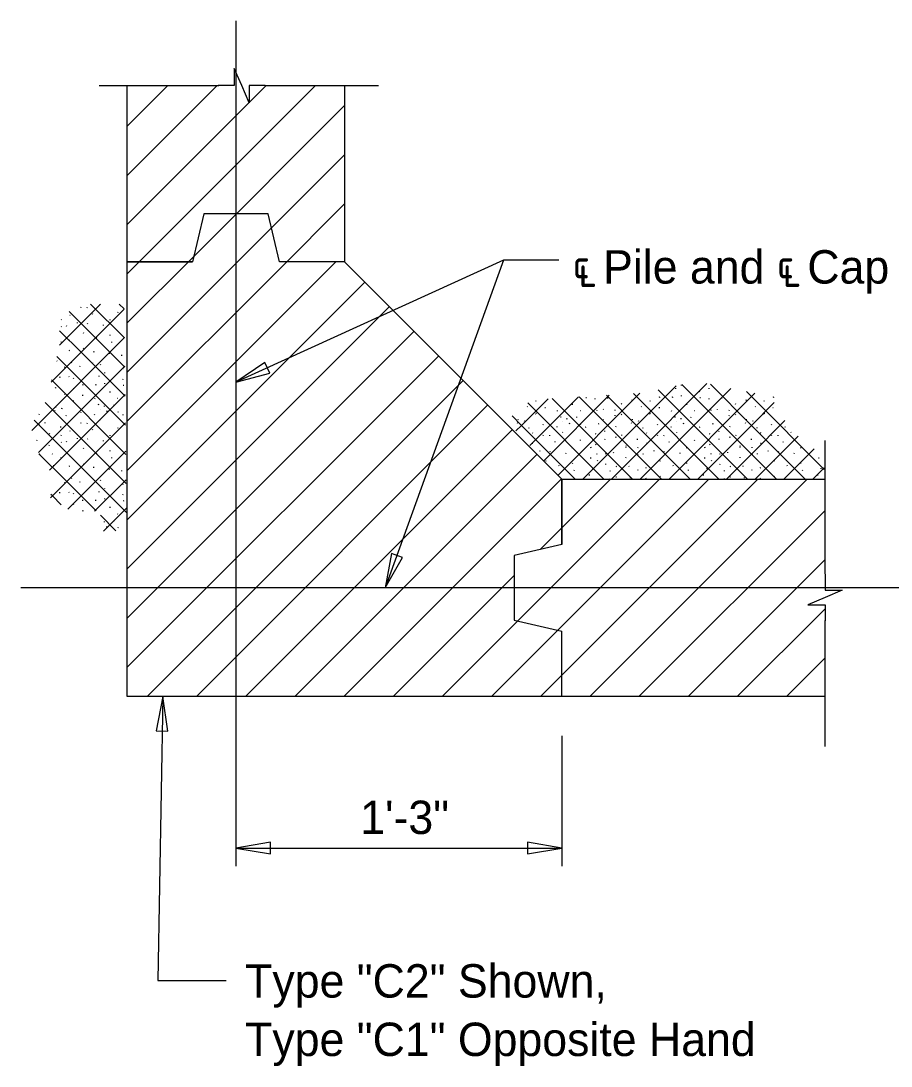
# Model space of a CAD drawing. Extents: x 0.4 to 30.4, y 0.1 to 19.4.
# Drawn here: x 0.429 to 4.371, y 0.449 to 5.182 of the extents above; entities that cross this region are included whole.
import ezdxf

# ---------------------------------------------------------------- set-up
doc = ezdxf.new("R2010")
doc.units = 0
for name, color, linetype in [('Dimension', 7, 'Continuous'), ('Miscellaneous', 7, 'Continuous'), ('SheetPileConc', 7, 'Continuous'), ('TextStructures', 7, 'Continuous')]:
    doc.layers.add(name, color=color, linetype=linetype)

msp = doc.modelspace()

# ---------------------------------------------------------------- linework, layer by layer
at = {"layer": 'Dimension'}
for p, q in [((0.7839, 4.8887), (1.3252, 4.8887)), ((1.5358, 4.8887), (2.0493, 4.8887)), ((2.6158, 4.0988), (1.4035, 3.5464)), ((2.6158, 4.0988), (2.0793, 2.6144)), ((2.8656, 4.0988), (2.6158, 4.0988)), ((4.0715, 2.6773), (4.0715, 3.2816)), ((4.0715, 1.8953), (4.0715, 2.4666)), ((2.8801, 1.9439), (2.8801, 1.3534)), ((1.4035, 1.4362), (2.8801, 1.4362))]:
    msp.add_line(p, q, dxfattribs=at)
for points in [[(1.5355, 4.8887), (1.463, 4.8887), (1.463, 4.8112), (1.4293, 4.8887), (1.3955, 4.9662), (1.3955, 4.8887), (1.323, 4.8887)], [(4.0715, 2.677), (4.0715, 2.6045), (4.149, 2.6045), (4.0715, 2.5708), (3.994, 2.537), (4.0715, 2.537), (4.0715, 2.4645)], [(1.0723, 2.1223), (1.0492, 0.8364), (1.3598, 0.8364)]]:
    msp.add_lwpolyline(points, dxfattribs=at)
for points in [[(1.4035, 3.5464), (1.5566, 3.5871), (1.5347, 3.6353)], [(2.0793, 2.6145), (2.1573, 2.7524), (2.1075, 2.7704)], [(1.0723, 2.1223), (1.0422, 1.9668), (1.0951, 1.9655)], [(1.4035, 1.4362), (1.5597, 1.4097), (1.5597, 1.4626)], [(2.8801, 1.4362), (2.7239, 1.4626), (2.7239, 1.4097)]]:
    msp.add_lwpolyline(points, close=True, dxfattribs=at)
at = {"layer": 'Miscellaneous'}
for p, q in [((1.4035, 5.1817), (1.4035, 1.3534)), ((0.9113, 4.2594), (1.5406, 4.8887)), ((0.9113, 4.4822), (1.3179, 4.8887)), ((0.9113, 4.7049), (1.0951, 4.8887)), ((0.9114, 4.0368), (1.7633, 4.8887)), ((1.2123, 4.1149), (1.8957, 4.7984)), ((1.5642, 4.2441), (1.8957, 4.5756)), ((1.5901, 4.0472), (1.8957, 4.3529)), ((0.9114, 3.5913), (1.5642, 4.2441)), ((0.9114, 3.8141), (1.2123, 4.1149)), ((0.9114, 3.1458), (1.8565, 4.091)), ((0.9114, 3.3685), (1.6339, 4.091)), ((0.9114, 2.9231), (1.9875, 3.9992)), ((0.604, 3.7137), (0.7898, 3.8996)), ((0.7005, 3.8838), (0.702, 3.8868)), ((0.7299, 3.8821), (0.7307, 3.8852)), ((0.8981, 3.7461), (0.7446, 3.8996)), ((0.7888, 3.8974), (0.788, 3.8989)), ((0.8965, 3.8779), (0.8748, 3.8996)), ((0.9114, 2.7004), (2.0989, 3.8879)), ((0.8323, 3.6816), (0.6482, 3.8658)), ((0.6532, 3.847), (0.6509, 3.8478)), ((0.7021, 3.6816), (0.8965, 3.8761)), ((0.7538, 3.8539), (0.7545, 3.8569)), ((0.8688, 3.8608), (0.8696, 3.8638)), ((0.614, 3.7974), (0.611, 3.7966)), ((0.6121, 3.828), (0.6127, 3.8303)), ((0.6366, 3.7989), (0.6373, 3.8019)), ((0.6854, 3.8124), (0.6862, 3.8154)), ((0.7316, 3.8103), (0.7331, 3.8133)), ((0.8031, 3.8019), (0.8038, 3.8049)), ((0.8331, 3.8259), (0.8339, 3.8289)), ((0.7021, 3.6816), (0.6048, 3.7789)), ((0.7122, 3.7681), (0.7137, 3.7711)), ((0.773, 3.7447), (0.7715, 3.747)), ((0.8323, 3.6816), (0.8981, 3.7474)), ((0.8331, 3.7567), (0.8339, 3.7597)), ((0.9113, 2.4776), (2.2102, 3.7765)), ((0.6117, 3.7267), (0.6133, 3.7297)), ((0.6501, 3.7364), (0.6471, 3.7349)), ((0.7138, 3.6974), (0.7123, 3.6996)), ((0.8407, 3.7248), (0.8415, 3.7277)), ((0.5719, 3.4211), (0.8323, 3.6816)), ((0.5719, 3.5514), (0.7021, 3.6816)), ((0.9029, 3.3506), (0.5922, 3.6613)), ((0.6501, 3.689), (0.6471, 3.6876)), ((0.9013, 3.4824), (0.7021, 3.6816)), ((0.7609, 3.6831), (0.7572, 3.6823)), ((0.8301, 3.674), (0.8309, 3.6771)), ((0.8997, 3.6142), (0.8323, 3.6816)), ((0.8858, 3.6657), (0.8865, 3.6688)), ((0.9113, 2.2548), (2.3216, 3.6651)), ((0.5719, 3.2909), (0.8996, 3.6187)), ((0.5937, 3.641), (0.5922, 3.6417)), ((0.6283, 3.6138), (0.6253, 3.6124)), ((0.6599, 3.6327), (0.6591, 3.6342)), ((0.6967, 3.6161), (0.6974, 3.6191)), ((0.7541, 3.6321), (0.7549, 3.6351)), ((0.7903, 3.6244), (0.791, 3.6274)), ((0.891, 3.6056), (0.8925, 3.6086)), ((0.566, 3.5455), (0.5719, 3.5514)), ((0.5719, 3.5514), (0.5682, 3.5551)), ((0.9045, 3.2188), (0.5719, 3.5514)), ((0.6065, 3.568), (0.6028, 3.5673)), ((0.6486, 3.5695), (0.6471, 3.5718)), ((0.6673, 3.5627), (0.6689, 3.5657)), ((0.7835, 3.5718), (0.7842, 3.5748)), ((0.8091, 3.5868), (0.8098, 3.5898)), ((0.891, 3.5582), (0.8925, 3.5612)), ((1.0015, 2.1223), (2.433, 3.5537)), ((0.5854, 3.5199), (0.5869, 3.5229)), ((0.5869, 3.5184), (0.5877, 3.5214)), ((0.6673, 3.5153), (0.6689, 3.5184)), ((0.7108, 3.5334), (0.707, 3.5327)), ((0.77, 3.5334), (0.7662, 3.5327)), ((0.8091, 3.5386), (0.8098, 3.5417)), ((0.8963, 3.5312), (0.8933, 3.5304)), ((3.2174, 3.2197), (3.5368, 3.5392)), ((3.2174, 3.3499), (3.3973, 3.5299)), ((3.2349, 3.107), (3.6452, 3.5173)), ((3.721, 3.1068), (3.3165, 3.5114)), ((3.3954, 3.5158), (3.3961, 3.5188)), ((3.421, 3.5308), (3.4217, 3.5338)), ((3.7383, 3.2197), (3.4224, 3.5356)), ((3.5029, 3.5023), (3.5044, 3.5053)), ((3.5473, 3.5158), (3.5473, 3.5188)), ((3.7383, 3.3499), (3.5521, 3.5361)), ((3.7383, 3.4802), (3.7153, 3.5032)), ((0.5719, 3.1607), (0.9012, 3.4901)), ((0.6283, 3.4898), (0.6268, 3.4921)), ((0.6666, 3.4575), (0.6659, 3.459)), ((0.6697, 3.4597), (0.6666, 3.4597)), ((0.7108, 3.486), (0.707, 3.4853)), ((0.7643, 3.4703), (0.7651, 3.4733)), ((0.8346, 3.5011), (0.8301, 3.5011)), ((0.8685, 3.4718), (0.867, 3.4725)), ((2.6966, 3.3499), (2.8168, 3.4702)), ((2.7351, 3.2583), (2.9555, 3.4787)), ((2.7623, 3.4594), (2.7639, 3.4624)), ((2.7987, 3.1917), (3.0942, 3.4872)), ((3.1999, 3.107), (2.8357, 3.4714)), ((2.8624, 3.1251), (3.2174, 3.4802)), ((3.2174, 3.2197), (2.9583, 3.4789)), ((2.9913, 3.4752), (2.9883, 3.4745)), ((3.0304, 3.4684), (3.0304, 3.4714)), ((3.2174, 3.3499), (3.081, 3.4864)), ((3.089, 3.4737), (3.0853, 3.4729)), ((3.1973, 3.4639), (3.1988, 3.4669)), ((3.1988, 3.4624), (3.1995, 3.4654)), ((3.2174, 3.4802), (3.2037, 3.4939)), ((3.2174, 3.4802), (3.2329, 3.4957)), ((3.5908, 3.1068), (3.2174, 3.4802)), ((3.2792, 3.4594), (3.2808, 3.4624)), ((3.3227, 3.4775), (3.3189, 3.4767)), ((3.365, 3.1069), (3.7383, 3.4802)), ((3.3819, 3.4775), (3.3781, 3.4767)), ((3.421, 3.4827), (3.4217, 3.4857)), ((3.5082, 3.4752), (3.5052, 3.4745)), ((3.5473, 3.4684), (3.5473, 3.4714)), ((3.6059, 3.4737), (3.6022, 3.4729)), ((3.7142, 3.4639), (3.7157, 3.4669)), ((3.7157, 3.4624), (3.7164, 3.4654)), ((3.7383, 3.4802), (3.7535, 3.4955)), ((4.0676, 3.1508), (3.7383, 3.4802)), ((3.7961, 3.4594), (3.7977, 3.4624)), ((3.8396, 3.4775), (3.8358, 3.4767)), ((0.4782, 3.3274), (0.5719, 3.4212)), ((0.5719, 3.4211), (0.5387, 3.4543)), ((0.8323, 3.1607), (0.5719, 3.4212)), ((0.5832, 3.4154), (0.5847, 3.4184)), ((0.5869, 3.4312), (0.5877, 3.4342)), ((0.6155, 3.4251), (0.617, 3.4289)), ((0.7005, 3.4079), (0.702, 3.4109)), ((0.782, 3.4439), (0.7783, 3.4432)), ((0.7888, 3.4214), (0.7883, 3.4222)), ((0.8076, 3.4349), (0.8083, 3.4379)), ((0.8189, 3.4131), (0.8204, 3.4169)), ((0.852, 3.4417), (0.8527, 3.4446)), ((0.8693, 3.4101), (0.8708, 3.4131)), ((1.2243, 2.1223), (2.5443, 3.4424)), ((2.7233, 3.4338), (2.7218, 3.4361)), ((3.0697, 3.1071), (2.725, 3.4518)), ((2.8058, 3.4301), (2.802, 3.4293)), ((2.8593, 3.4143), (2.8601, 3.4173)), ((2.9296, 3.4451), (2.9251, 3.4451)), ((2.9635, 3.4158), (2.962, 3.4165)), ((3.0386, 3.4173), (3.0394, 3.4203)), ((3.068, 3.4218), (3.0673, 3.4233)), ((3.1206, 3.4173), (3.1214, 3.4203)), ((3.1484, 3.4459), (3.1507, 3.4488)), ((3.2402, 3.4338), (3.2387, 3.4361)), ((3.3227, 3.4301), (3.3189, 3.4293)), ((3.3762, 3.4143), (3.377, 3.4173)), ((3.4465, 3.4451), (3.442, 3.4451)), ((3.4804, 3.4158), (3.4789, 3.4165)), ((3.5555, 3.4173), (3.5563, 3.4203)), ((3.5849, 3.4218), (3.5842, 3.4233)), ((3.6375, 3.4173), (3.6383, 3.4203)), ((3.6653, 3.4459), (3.6676, 3.4488)), ((3.7383, 3.3499), (3.8418, 3.4535)), ((3.7571, 3.4338), (3.7556, 3.4361)), ((3.837, 3.4295), (3.8358, 3.4293)), ((0.5719, 3.2909), (0.4889, 3.374)), ((0.5117, 3.3988), (0.5133, 3.4025)), ((0.5388, 3.3598), (0.5395, 3.3627)), ((0.6351, 3.3928), (0.6358, 3.3958)), ((0.6532, 3.371), (0.6509, 3.3717)), ((0.7005, 3.3605), (0.702, 3.3635)), ((0.7021, 3.1607), (0.9028, 3.3614)), ((0.7299, 3.3588), (0.7307, 3.3618)), ((0.7628, 3.3973), (0.7635, 3.4004)), ((0.7888, 3.374), (0.788, 3.3755)), ((0.8933, 3.3973), (0.8896, 3.3965)), ((2.6966, 3.3499), (2.654, 3.3926)), ((2.6782, 3.3594), (2.6797, 3.3624)), ((2.6819, 3.3752), (2.6827, 3.3782)), ((2.7105, 3.3691), (2.712, 3.3729)), ((2.7616, 3.4015), (2.7609, 3.403)), ((2.7647, 3.4038), (2.7616, 3.4038)), ((2.877, 3.3879), (2.8732, 3.3872)), ((2.8838, 3.3654), (2.8833, 3.3662)), ((2.9025, 3.3789), (2.9033, 3.382)), ((2.9139, 3.3571), (2.9154, 3.3609)), ((2.9469, 3.3857), (2.9477, 3.3887)), ((3.068, 3.3745), (3.0673, 3.376)), ((3.1206, 3.3932), (3.1214, 3.3962)), ((3.1484, 3.3985), (3.1507, 3.4015)), ((3.1951, 3.3594), (3.1966, 3.3624)), ((3.1988, 3.3752), (3.1995, 3.3782)), ((3.2274, 3.3691), (3.2289, 3.3729)), ((3.2785, 3.4015), (3.2778, 3.403)), ((3.2816, 3.4038), (3.2785, 3.4038)), ((3.3939, 3.3879), (3.3901, 3.3872)), ((3.4007, 3.3654), (3.4002, 3.3662)), ((3.4194, 3.3789), (3.4202, 3.382)), ((3.4308, 3.3571), (3.4323, 3.3609)), ((3.4638, 3.3857), (3.4646, 3.3887)), ((3.5849, 3.3745), (3.5842, 3.376)), ((3.6375, 3.3932), (3.6383, 3.3962)), ((3.6653, 3.3985), (3.6676, 3.4015)), ((3.712, 3.3594), (3.7134, 3.3624)), ((3.7157, 3.3752), (3.7164, 3.3782)), ((3.7383, 3.2197), (3.89, 3.3715)), ((3.7443, 3.3691), (3.7458, 3.3729)), ((3.7954, 3.4015), (3.7947, 3.403)), ((3.7985, 3.4038), (3.7954, 3.4038)), ((0.5117, 3.3514), (0.5133, 3.3552)), ((0.5591, 3.3116), (0.5599, 3.3146)), ((0.611, 3.3424), (0.6072, 3.3417)), ((0.6532, 3.3236), (0.6509, 3.3244)), ((0.7538, 3.3305), (0.7545, 3.3335)), ((0.8688, 3.3375), (0.8696, 3.3404)), ((1.447, 2.1223), (2.6557, 3.331)), ((2.6714, 3.3248), (2.6966, 3.35)), ((2.9394, 3.1071), (2.6966, 3.35)), ((2.7301, 3.3368), (2.7308, 3.3399)), ((2.7482, 3.3151), (2.7459, 3.3158)), ((2.7955, 3.3519), (2.797, 3.3549)), ((2.8578, 3.3414), (2.8585, 3.3444)), ((2.8838, 3.318), (2.883, 3.3195)), ((2.9643, 3.3541), (2.9658, 3.3571)), ((2.9746, 3.1071), (3.2174, 3.35)), ((2.9883, 3.3414), (2.9846, 3.3406)), ((3.0477, 3.3571), (3.044, 3.3556)), ((3.074, 3.3226), (3.0748, 3.3255)), ((3.1236, 3.3429), (3.1252, 3.3466)), ((3.4605, 3.1069), (3.2174, 3.35)), ((3.2469, 3.3368), (3.2477, 3.3399)), ((3.265, 3.3151), (3.2628, 3.3158)), ((3.3124, 3.3519), (3.3139, 3.3549)), ((3.3747, 3.3414), (3.3754, 3.3444)), ((3.4007, 3.318), (3.3999, 3.3195)), ((3.4812, 3.3541), (3.4827, 3.3571)), ((3.4952, 3.1069), (3.7383, 3.35)), ((3.5052, 3.3414), (3.5015, 3.3406)), ((3.5646, 3.3571), (3.5608, 3.3556)), ((3.5909, 3.3226), (3.5917, 3.3255)), ((3.6405, 3.3429), (3.6421, 3.3466)), ((3.9816, 3.1066), (3.7383, 3.35)), ((3.7638, 3.3368), (3.7646, 3.3399)), ((3.7819, 3.3151), (3.7797, 3.3158)), ((3.8293, 3.3519), (3.8308, 3.3549)), ((3.8916, 3.3414), (3.8923, 3.3444)), ((3.9176, 3.318), (3.9168, 3.3195)), ((0.5019, 3.2812), (0.5027, 3.2841)), ((0.5089, 3.228), (0.5719, 3.2909)), ((0.5576, 3.3063), (0.5591, 3.3094)), ((0.7021, 3.1607), (0.5719, 3.2909)), ((0.614, 3.274), (0.611, 3.2732)), ((0.6121, 3.3046), (0.6129, 3.3076)), ((0.6366, 3.2755), (0.6373, 3.2785)), ((0.6854, 3.2891), (0.6862, 3.2921)), ((0.7316, 3.2869), (0.7331, 3.2899)), ((0.8031, 3.2785), (0.8038, 3.2815)), ((0.8331, 3.3025), (0.8339, 3.3056)), ((2.7482, 3.2677), (2.7459, 3.2684)), ((2.7955, 3.3045), (2.797, 3.3075)), ((2.8249, 3.3028), (2.8257, 3.3059)), ((2.8488, 3.2746), (2.8495, 3.2776)), ((2.9638, 3.2815), (2.9646, 3.2845)), ((3.0342, 3.3098), (3.0319, 3.3121)), ((3.0748, 3.2857), (3.0755, 3.2887)), ((3.1236, 3.2955), (3.1252, 3.2992)), ((3.1507, 3.3038), (3.1514, 3.3067)), ((3.2229, 3.2864), (3.2191, 3.2857)), ((3.265, 3.2677), (3.2628, 3.2684)), ((3.3124, 3.3045), (3.3139, 3.3075)), ((3.3418, 3.3028), (3.3426, 3.3059)), ((3.3657, 3.2746), (3.3664, 3.2776)), ((3.4807, 3.2815), (3.4815, 3.2845)), ((3.5511, 3.3098), (3.5488, 3.3121)), ((3.5917, 3.2857), (3.5924, 3.2887)), ((3.6405, 3.2955), (3.6421, 3.2992)), ((3.6676, 3.3038), (3.6683, 3.3067)), ((3.7398, 3.2864), (3.736, 3.2857)), ((3.7555, 3.1068), (3.9506, 3.3019)), ((3.7819, 3.2677), (3.7797, 3.2684)), ((3.8293, 3.3045), (3.8308, 3.3075)), ((3.8587, 3.3028), (3.8595, 3.3059)), ((3.8826, 3.2746), (3.8833, 3.2776)), ((0.5716, 3.161), (0.5109, 3.2217)), ((0.5147, 3.2191), (0.5119, 3.2184)), ((0.5576, 3.259), (0.5591, 3.262)), ((0.5727, 3.2191), (0.5704, 3.2214)), ((0.7122, 3.2447), (0.7137, 3.2477)), ((0.773, 3.2214), (0.7715, 3.2236)), ((0.8323, 3.1607), (0.9043, 3.2327)), ((0.8331, 3.2334), (0.8339, 3.2364)), ((1.6697, 2.1223), (2.7671, 3.2197)), ((2.7804, 3.2331), (2.7812, 3.2361)), ((2.8266, 3.2309), (2.8281, 3.2339)), ((2.8981, 3.2225), (2.8988, 3.2255)), ((2.9281, 3.2466), (2.9288, 3.2496)), ((3.0116, 3.2496), (3.0078, 3.2488)), ((3.0342, 3.2624), (3.0319, 3.2647)), ((3.0386, 3.2203), (3.0394, 3.2233)), ((3.0785, 3.2203), (3.0792, 3.2233)), ((3.1048, 3.1071), (3.2174, 3.2197)), ((3.1138, 3.2252), (3.1146, 3.2281)), ((3.1695, 3.2503), (3.171, 3.2534)), ((3.171, 3.2556), (3.1718, 3.2587)), ((3.3302, 3.107), (3.2174, 3.2197)), ((3.224, 3.2486), (3.2247, 3.2516)), ((3.2484, 3.2195), (3.2492, 3.2225)), ((3.2973, 3.2331), (3.2981, 3.2361)), ((3.3435, 3.2309), (3.345, 3.2339)), ((3.4149, 3.2225), (3.4157, 3.2255)), ((3.445, 3.2466), (3.4457, 3.2496)), ((3.5285, 3.2496), (3.5247, 3.2488)), ((3.5511, 3.2624), (3.5488, 3.2647)), ((3.5555, 3.2203), (3.5563, 3.2233)), ((3.5954, 3.2203), (3.5961, 3.2233)), ((3.6253, 3.1068), (3.7383, 3.2197)), ((3.6307, 3.2252), (3.6315, 3.2281)), ((3.6864, 3.2503), (3.6879, 3.2534)), ((3.6879, 3.2556), (3.6886, 3.2587)), ((3.8513, 3.1067), (3.7383, 3.2197)), ((3.7409, 3.2486), (3.7416, 3.2516)), ((3.7653, 3.2195), (3.7661, 3.2225)), ((3.8142, 3.2331), (3.815, 3.2361)), ((3.8604, 3.2309), (3.8619, 3.2339)), ((3.8856, 3.1067), (4.0221, 3.2432)), ((3.9318, 3.2225), (3.9326, 3.2255)), ((3.9619, 3.2466), (3.9626, 3.2496)), ((0.6117, 3.2033), (0.6133, 3.2063)), ((0.6501, 3.2131), (0.6471, 3.2116)), ((0.7138, 3.174), (0.7123, 3.1762)), ((0.8407, 3.2014), (0.8415, 3.2044)), ((2.8072, 3.1887), (2.8087, 3.1917)), ((2.9281, 3.1774), (2.9288, 3.1804)), ((3.0116, 3.2023), (3.0078, 3.2015)), ((3.0412, 3.1901), (3.0419, 3.193)), ((3.0785, 3.1729), (3.0792, 3.1759)), ((3.1695, 3.203), (3.171, 3.206)), ((3.2259, 3.218), (3.2229, 3.2173)), ((3.3241, 3.1887), (3.3256, 3.1917)), ((3.445, 3.1774), (3.4457, 3.1804)), ((3.5285, 3.2023), (3.5247, 3.2015)), ((3.558, 3.1901), (3.5588, 3.193)), ((3.5954, 3.1729), (3.5961, 3.1759)), ((3.6864, 3.203), (3.6879, 3.206)), ((3.7428, 3.218), (3.7398, 3.2173)), ((3.841, 3.1887), (3.8425, 3.1917)), ((3.9619, 3.1774), (3.9626, 3.1804)), ((4.0454, 3.2023), (4.0416, 3.2015)), ((0.5584, 3.1472), (0.5719, 3.1607)), ((0.7699, 2.9627), (0.5719, 3.1607)), ((0.5719, 3.0305), (0.7021, 3.1607)), ((0.5779, 3.1673), (0.5787, 3.1702)), ((0.6423, 2.9707), (0.8323, 3.1607)), ((0.6501, 3.1657), (0.6471, 3.1643)), ((0.9077, 2.9551), (0.7021, 3.1607)), ((0.7609, 3.1598), (0.7572, 3.159)), ((0.8301, 3.1506), (0.8309, 3.1537)), ((0.9061, 3.0869), (0.8323, 3.1607)), ((0.8858, 3.1424), (0.8865, 3.1454)), ((2.868, 3.1654), (2.8665, 3.1677)), ((2.9357, 3.1455), (2.9365, 3.1484)), ((3.0063, 3.1248), (3.0018, 3.124)), ((3.0199, 3.1534), (3.0206, 3.1563)), ((3.0988, 3.1421), (3.0995, 3.1451)), ((3.1266, 3.1632), (3.1236, 3.1624)), ((3.1846, 3.1632), (3.1823, 3.1654)), ((3.2236, 3.1473), (3.2252, 3.1503)), ((3.262, 3.1571), (3.259, 3.1556)), ((3.3849, 3.1654), (3.3834, 3.1677)), ((3.4526, 3.1455), (3.4534, 3.1484)), ((3.5232, 3.1248), (3.5187, 3.124)), ((3.5368, 3.1534), (3.5375, 3.1563)), ((3.6157, 3.1421), (3.6164, 3.1451)), ((3.6435, 3.1632), (3.6405, 3.1624)), ((3.7015, 3.1632), (3.6992, 3.1654)), ((3.7405, 3.1473), (3.7421, 3.1503)), ((3.7789, 3.1571), (3.7759, 3.1556)), ((3.9018, 3.1654), (3.9003, 3.1677)), ((3.9695, 3.1455), (3.9703, 3.1484)), ((4.0158, 3.1066), (4.067, 3.1579)), ((4.0401, 3.1248), (4.0356, 3.124)), ((4.0537, 3.1534), (4.0544, 3.1563)), ((0.6283, 3.0905), (0.6253, 3.0891)), ((0.6599, 3.1093), (0.6591, 3.1108)), ((0.6967, 3.0928), (0.6974, 3.0958)), ((0.7541, 3.1088), (0.7549, 3.1118)), ((0.7632, 2.9614), (0.9059, 3.1041)), ((0.7903, 3.101), (0.791, 3.1041)), ((0.891, 3.0822), (0.8925, 3.0853)), ((1.8925, 2.1223), (2.8785, 3.1083)), ((2.6804, 2.4647), (3.3223, 3.1066)), ((2.7807, 2.7879), (3.0995, 3.1066)), ((2.7834, 2.1223), (3.7678, 3.1066)), ((2.8606, 2.4222), (3.545, 3.1066)), ((3.0061, 2.1223), (3.9905, 3.1066)), ((3.0989, 3.1071), (3.0995, 3.1097)), ((3.1266, 3.1158), (3.1236, 3.115)), ((3.1898, 3.1113), (3.1906, 3.1143)), ((3.262, 3.1097), (3.259, 3.1083)), ((3.3257, 3.118), (3.3242, 3.1203)), ((3.6157, 3.1068), (3.6164, 3.1097)), ((3.6435, 3.1158), (3.6405, 3.115)), ((3.7067, 3.1113), (3.7075, 3.1143)), ((3.7789, 3.1097), (3.7759, 3.1083)), ((3.8426, 3.118), (3.8411, 3.1203)), ((0.5634, 3.022), (0.5719, 3.0305)), ((0.5719, 3.0305), (0.5653, 3.0371)), ((0.6119, 2.9905), (0.5719, 3.0305)), ((0.6065, 3.0447), (0.6028, 3.0439)), ((0.6486, 3.0462), (0.6471, 3.0484)), ((0.6673, 3.0394), (0.6689, 3.0424)), ((0.7835, 3.0484), (0.7842, 3.0514)), ((0.8091, 3.0635), (0.8098, 3.0665)), ((0.891, 3.0349), (0.8925, 3.0379)), ((0.6673, 2.992), (0.6689, 2.9951)), ((0.7108, 3.0101), (0.707, 3.0093)), ((0.77, 3.0101), (0.7662, 3.0093)), ((0.8091, 3.0153), (0.8098, 3.0184)), ((0.8963, 3.0078), (0.8933, 3.0071)), ((0.7108, 2.9627), (0.707, 2.9619)), ((0.8593, 2.8733), (0.7893, 2.9433)), ((0.8036, 2.8716), (0.9074, 2.9754)), ((0.8346, 2.9777), (0.8301, 2.9777)), ((0.8685, 2.9484), (0.867, 2.9492)), ((3.2289, 2.1223), (4.0715, 2.9649)), ((0.8076, 2.9115), (0.8083, 2.9146)), ((0.8189, 2.8897), (0.8204, 2.8935)), ((0.852, 2.9184), (0.8527, 2.9213)), ((0.8693, 2.8867), (0.8708, 2.8897)), ((3.4516, 2.1223), (4.0715, 2.7422)), ((2.1152, 2.1223), (2.6635, 2.6706)), ((4.0715, 2.6144), (0.4294, 2.6144)), ((4.4653, 2.6144), (4.0715, 2.6144)), ((3.6743, 2.1223), (4.0715, 2.5195)), ((2.3379, 2.1223), (2.6804, 2.4648)), ((2.5606, 2.1223), (2.8606, 2.4222)), ((3.8971, 2.1223), (4.0715, 2.2967))]:
    msp.add_line(p, q, dxfattribs=at)
at = {"layer": 'SheetPileConc'}
for p, q in [((0.9113, 4.091), (0.9113, 4.8887)), ((1.8957, 4.8887), (1.8957, 4.091)), ((1.2578, 4.3076), (1.2066, 4.091)), ((1.5492, 4.3076), (1.2578, 4.3076)), ((1.6004, 4.091), (1.5492, 4.3076)), ((0.9113, 2.1223), (0.9114, 4.091)), ((1.2066, 4.091), (0.9113, 4.091)), ((0.9113, 4.091), (1.2066, 4.091)), ((1.2067, 4.091), (0.9114, 4.091)), ((1.8957, 4.091), (1.6004, 4.091)), ((1.8957, 4.091), (1.6004, 4.091)), ((1.8957, 4.091), (1.6004, 4.091)), ((2.8801, 3.1067), (1.8957, 4.091)), ((2.8801, 2.8113), (2.8801, 3.1067)), ((2.8801, 3.1066), (2.8801, 2.8113)), ((2.8801, 3.1066), (4.0715, 3.1066)), ((2.8801, 2.8113), (2.6635, 2.7601)), ((2.6635, 2.7601), (2.6636, 2.4687)), ((2.6636, 2.4687), (2.8801, 2.4175)), ((2.8801, 2.1223), (2.8801, 2.4176)), ((2.8801, 2.1222), (2.8801, 2.4175)), ((2.8801, 2.1223), (0.9113, 2.1223)), ((4.0715, 2.1223), (2.8801, 2.1223))]:
    msp.add_line(p, q, dxfattribs=at)

# ---------------------------------------------------------------- texts
at = {"layer": 'TextStructures'}
for s, p in [('℄ Pile and ℄ Cap', (2.9282, 3.9922)), ('1\'-3"', (1.9661, 1.4996)), ('Type "C2" Shown,', (1.4449, 0.7589)), ('Type "C1" Opposite Hand', (1.4449, 0.4943))]:
    msp.add_text(s, height=0.1512, dxfattribs=at).set_placement(p)

doc.saveas('drawing.dxf')
